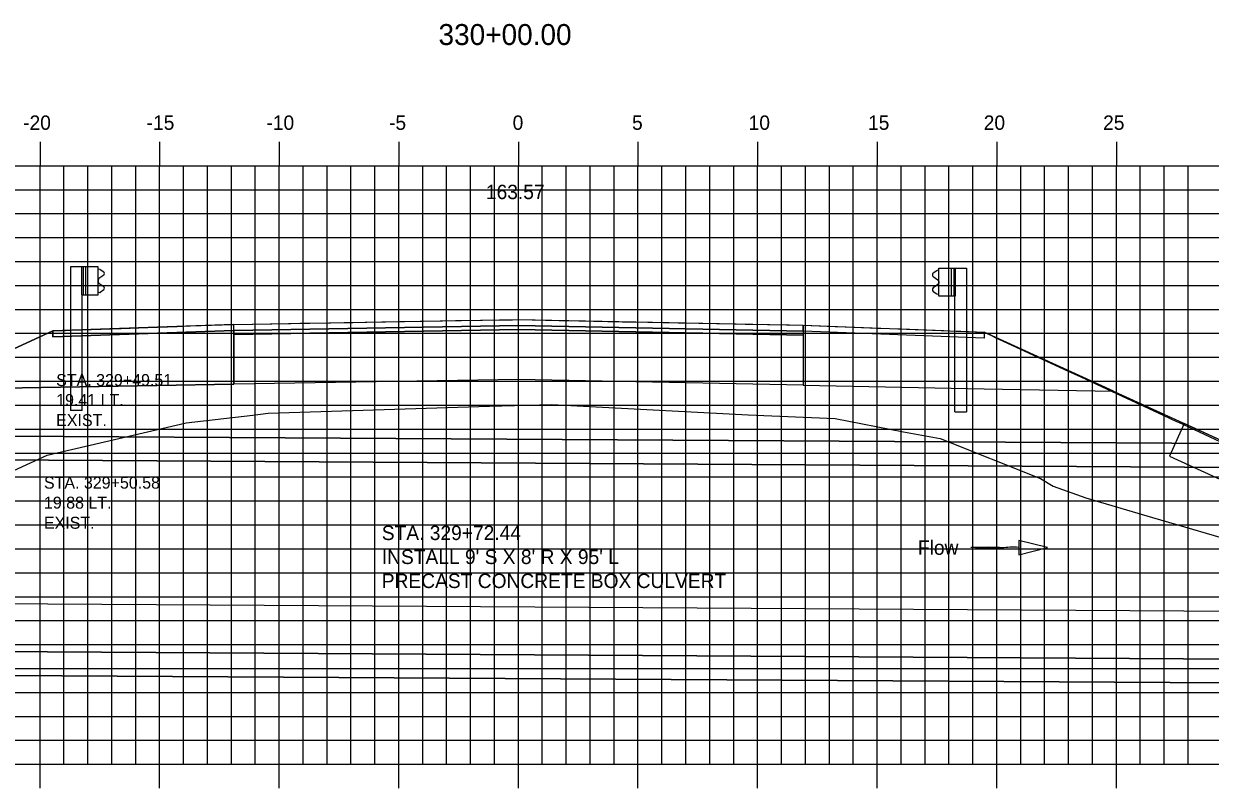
# Model space of a CAD drawing. Extents: x 1141202 to 1141372, y 608981 to 609091.
# Drawn here: x 1141264.83 to 1141314.44, y 609024.33 to 609056.27 of the extents above; entities that cross this region are included whole.
import ezdxf

# ---------------------------------------------------------------- set-up
doc = ezdxf.new("R2010")
doc.units = 0
for name, color, linetype in [('ANNOTATION', 7, 'Continuous'), ('D_Drainage_Culvert', 7, 'Continuous'), ('D_Guardrail_Beam_Lt', 7, 'Continuous'), ('D_Guardrail_Beam_Rt', 7, 'Continuous'), ('D_Guardrail_ConcBarrier', 7, 'Continuous'), ('D_Roadway_Centerline', 7, 'Continuous'), ('D_Roadway_Centerline_Text', 7, 'Continuous'), ('D_Roadway_Edge_Shoulder', 7, 'Continuous'), ('D_Roadway_Edge_TW', 7, 'Continuous'), ('D_Roadway_Pavement', 7, 'Continuous'), ('D_Roadway_SlopeLines', 7, 'Continuous'), ('D_Roadway_SubGrade', 7, 'Continuous'), ('D_Text_Monospaced', 7, 'Continuous'), ('H_V ANNOTATION', 7, 'Continuous'), ('MAJOR', 7, 'Continuous'), ('MINOR', 7, 'Continuous'), ('PATTERNING', 7, 'Continuous'), ('S_Roadway_Centerline', 7, 'Continuous'), ('WATER_DAM', 7, 'Continuous')]:
    doc.layers.add(name, color=color, linetype=linetype)

msp = doc.modelspace()

# ---------------------------------------------------------------- linework, layer by layer
for points in [[(1141264.248, 609042.614), (1141266.045, 609043.442), (1141266.046, 609043.442), (1141266.046, 609043.442), (1141266.454, 609043.456), (1141266.58, 609043.46), (1141266.817, 609043.469), (1141268.911, 609043.542), (1141270.019, 609043.581), (1141271.242, 609043.624), (1141271.801, 609043.644), (1141273.573, 609043.707), (1141273.583, 609043.707), (1141273.617, 609043.708), (1141275.902, 609043.747), (1141276.381, 609043.755), (1141276.526, 609043.757), (1141277.653, 609043.776), (1141278.232, 609043.786), (1141278.599, 609043.792), (1141279.11, 609043.801), (1141279.806, 609043.812), (1141280.561, 609043.825), (1141282.25, 609043.854), (1141282.889, 609043.864), (1141285.145, 609043.903), (1141285.217, 609043.904), (1141285.266, 609043.905), (1141285.514, 609043.909), (1141287.212, 609043.875), (1141287.544, 609043.868), (1141288.038, 609043.859), (1141289.871, 609043.822), (1141290.93, 609043.801), (1141292.198, 609043.776), (1141293.051, 609043.759), (1141294.524, 609043.73), (1141294.996, 609043.72), (1141296.849, 609043.684), (1141297.413, 609043.672), (1141298.76, 609043.621), (1141299.174, 609043.605), (1141300.539, 609043.553), (1141301.498, 609043.516), (1141303.307, 609043.447), (1141303.822, 609043.428), (1141304.016, 609043.42), (1141304.985, 609043.383)], [(1141305.345, 609043.216), (1141305.376, 609043.202), (1141305.396, 609043.193), (1141306.145, 609042.845), (1141307.41, 609042.26), (1141308.468, 609041.769), (1141309.026, 609041.511), (1141310.304, 609040.919), (1141310.791, 609040.694), (1141311.659, 609040.291), (1141312.468, 609039.917), (1141313.034, 609039.654), (1141313.113, 609039.618), (1141315.076, 609038.709), (1141315.434, 609038.543), (1141317.138, 609037.754), (1141317.755, 609037.468), (1141318.557, 609037.097), (1141320.075, 609036.394), (1141321.235, 609035.857), (1141322.395, 609035.32), (1141323.928, 609034.61), (1141324.715, 609034.246), (1141326.998, 609033.189)]]:
    msp.add_lwpolyline(points)
at = {"layer": 'D_Drainage_Culvert'}
for points in [[(1141240.936, 609030.185), (1141240.985, 609038.185), (1141240.991, 609039.185), (1141335.989, 609038.605), (1141335.983, 609037.605), (1141335.934, 609029.606), (1141335.916, 609026.606), (1141334.916, 609026.612), (1141334.928, 609028.612), (1141335.928, 609028.606), (1141240.93, 609029.185), (1141240.918, 609027.185), (1141241.918, 609027.179), (1141241.93, 609029.179)], [(1141240.934, 609030.185), (1141335.934, 609029.606), (1141335.983, 609037.605), (1141240.985, 609038.185), (1141240.936, 609030.185)]]:
    msp.add_lwpolyline(points, dxfattribs=at)
at = {"layer": 'D_Guardrail_Beam_Lt'}
for p, q in [((1141266.783, 609046.107), (1141266.783, 609040.107)), ((1141267.254, 609046.107), (1141266.783, 609046.107)), ((1141267.941, 609046.107), (1141267.254, 609046.107)), ((1141267.254, 609046.107), (1141267.254, 609044.941)), ((1141267.316, 609046.107), (1141267.316, 609044.941)), ((1141267.42, 609046.107), (1141267.42, 609044.941)), ((1141267.941, 609044.941), (1141267.941, 609046.107)), ((1141267.941, 609046.024), (1141268.015, 609046.009)), ((1141268.031, 609046.003), (1141268.175, 609045.903)), ((1141267.946, 609045.559), (1141267.946, 609045.489)), ((1141268.175, 609045.76), (1141267.979, 609045.624)), ((1141267.979, 609045.425), (1141268.175, 609045.288)), ((1141267.254, 609044.941), (1141267.941, 609044.941)), ((1141267.274, 609040.107), (1141267.274, 609044.941)), ((1141268.015, 609045.039), (1141267.941, 609045.024)), ((1141268.175, 609045.145), (1141268.031, 609045.045)), ((1141267.274, 609040.107), (1141266.783, 609040.107))]:
    msp.add_line(p, q, dxfattribs=at)
for centre, major_axis, start_param, end_param in [((1141268.007, 609045.969), (0.0417, 0), 0.959931, 1.376053), ((1141268.024, 609045.559), (-0.0789, 0), 5.323254, 6.283185), ((1141268.024, 609045.489), (-0.0789, 0), 6.283185, 7.243116), ((1141268.124, 609045.831), (0.0877, 0), 5.323254, 7.243116), ((1141268.007, 609045.079), (0.0417, 0), 4.907132, 5.323254), ((1141268.124, 609045.217), (0.0877, 0), 5.323254, 7.243116)]:
    msp.add_ellipse(centre, major_axis=major_axis, ratio=0.995501, start_param=start_param, end_param=end_param, dxfattribs=at)
at = {"layer": 'D_Guardrail_Beam_Rt'}
for p, q in [((1141303.003, 609045.946), (1141302.86, 609045.846)), ((1141303.093, 609045.967), (1141303.019, 609045.953)), ((1141302.86, 609045.703), (1141303.055, 609045.567)), ((1141303.089, 609045.503), (1141303.089, 609045.432)), ((1141303.055, 609045.368), (1141302.86, 609045.232)), ((1141302.86, 609045.089), (1141303.003, 609044.989)), ((1141303.019, 609044.982), (1141303.093, 609044.967))]:
    msp.add_line(p, q, dxfattribs=at)
for centre, major_axis, start_param, end_param in [((1141303.027, 609045.912), (-0.0417, 0), 4.907132, 5.323254), ((1141302.91, 609045.775), (-0.0877, 0), 5.323254, 7.243116), ((1141303.01, 609045.503), (0.0789, 0), 0, 0.959931), ((1141303.01, 609045.432), (0.0789, 0), 5.323254, 6.283185), ((1141302.91, 609045.16), (-0.0877, 0), 5.323254, 7.243116), ((1141303.027, 609045.023), (-0.0417, 0), 0.959931, 1.376053)]:
    msp.add_ellipse(centre, major_axis=major_axis, ratio=0.995501, start_param=start_param, end_param=end_param, dxfattribs=at)
at = {"layer": 'D_Guardrail_ConcBarrier'}
for p, q in [((1141303.093, 609046.051), (1141303.78, 609046.051)), ((1141303.093, 609044.884), (1141303.093, 609046.051)), ((1141303.614, 609046.051), (1141303.614, 609044.884)), ((1141303.718, 609046.051), (1141303.718, 609044.884)), ((1141303.78, 609046.051), (1141304.251, 609046.051)), ((1141303.78, 609046.051), (1141303.78, 609044.884)), ((1141304.251, 609046.051), (1141304.251, 609040.051)), ((1141303.78, 609044.884), (1141303.093, 609044.884)), ((1141303.76, 609040.051), (1141303.76, 609044.884)), ((1141303.76, 609040.051), (1141304.251, 609040.051))]:
    msp.add_line(p, q, dxfattribs=at)
at = {"layer": 'D_Roadway_Edge_Shoulder'}
for points in [[(1141273.617, 609043.708), (1141266.046, 609043.442), (1141266.046, 609043.192), (1141273.617, 609043.458)], [(1141297.413, 609043.672), (1141304.985, 609043.383), (1141304.985, 609043.133), (1141297.413, 609043.422)]]:
    msp.add_lwpolyline(points, close=True, dxfattribs=at)
at = {"layer": 'D_Roadway_Edge_TW'}
msp.add_lwpolyline([(1141273.617, 609043.458), (1141273.617, 609043.708), (1141285.514, 609043.909), (1141297.413, 609043.672), (1141297.413, 609043.422), (1141285.514, 609043.659)], close=True, dxfattribs=at)
at = {"layer": 'D_Roadway_Pavement'}
msp.add_lwpolyline([(1141273.617, 609043.291), (1141273.617, 609043.458), (1141285.514, 609043.659), (1141297.413, 609043.422), (1141297.413, 609043.256), (1141285.514, 609043.492)], close=True, dxfattribs=at)
at = {"layer": 'D_Roadway_SlopeLines'}
msp.add_lwpolyline([(1141273.617, 609041.209), (1141260.721, 609040.991), (1141266.047, 609043.443), (1141266.047, 609043.193), (1141273.617, 609043.459)], close=True, dxfattribs=at)
at = {"layer": 'D_Roadway_SubGrade'}
for points in [[(1141273.617, 609043.291), (1141273.617, 609043.458), (1141266.046, 609043.192), (1141266.046, 609043.442), (1141266.045, 609043.442), (1141260.728, 609040.994), (1141273.617, 609041.208)], [(1141273.617, 609041.208), (1141273.617, 609043.291), (1141285.514, 609043.492), (1141297.413, 609043.256), (1141297.413, 609041.172), (1141285.514, 609041.409)], [(1141304.985, 609041.023), (1141310.388, 609040.917), (1141304.985, 609043.383), (1141304.985, 609043.133), (1141297.413, 609043.422), (1141297.413, 609041.172)]]:
    msp.add_lwpolyline(points, close=True, dxfattribs=at)
msp.add_lwpolyline([(1141304.985, 609043.383), (1141320.188, 609036.444), (1141330.629, 609031.638)], dxfattribs=at)
at = {"layer": 'MAJOR'}
for p, q in [((1141265.514, 609051.337), (1141265.514, 609050.335)), ((1141270.514, 609051.337), (1141270.514, 609050.335)), ((1141275.514, 609051.337), (1141275.514, 609050.335)), ((1141280.514, 609051.337), (1141280.514, 609050.335)), ((1141285.514, 609051.337), (1141285.514, 609050.335)), ((1141290.514, 609051.337), (1141290.514, 609050.335)), ((1141295.514, 609051.337), (1141295.514, 609050.335)), ((1141300.514, 609051.337), (1141300.514, 609050.335)), ((1141305.514, 609051.337), (1141305.514, 609050.335)), ((1141310.514, 609051.337), (1141310.514, 609050.335)), ((1141215.514, 609050.335), (1141355.514, 609050.335)), ((1141215.514, 609050.335), (1141355.514, 609050.335)), ((1141265.514, 609025.335), (1141265.514, 609050.335)), ((1141270.514, 609025.335), (1141270.514, 609050.335)), ((1141275.514, 609025.335), (1141275.514, 609050.335)), ((1141280.514, 609025.335), (1141280.514, 609050.335)), ((1141285.514, 609025.335), (1141285.514, 609050.335)), ((1141290.514, 609025.335), (1141290.514, 609050.335)), ((1141295.514, 609025.335), (1141295.514, 609050.335)), ((1141300.514, 609025.335), (1141300.514, 609050.335)), ((1141305.514, 609025.335), (1141305.514, 609050.335)), ((1141310.514, 609025.335), (1141310.514, 609050.335)), ((1141215.514, 609045.335), (1141355.514, 609045.335)), ((1141215.514, 609040.335), (1141355.514, 609040.335)), ((1141215.514, 609035.335), (1141355.514, 609035.335)), ((1141215.514, 609030.335), (1141355.514, 609030.335)), ((1141215.514, 609025.335), (1141355.514, 609025.335)), ((1141215.514, 609025.335), (1141355.514, 609025.335)), ((1141265.514, 609024.333), (1141265.514, 609025.335)), ((1141270.514, 609024.333), (1141270.514, 609025.335)), ((1141275.514, 609024.333), (1141275.514, 609025.335)), ((1141280.514, 609024.333), (1141280.514, 609025.335)), ((1141285.514, 609024.333), (1141285.514, 609025.335)), ((1141290.514, 609024.333), (1141290.514, 609025.335)), ((1141295.514, 609024.333), (1141295.514, 609025.335)), ((1141300.514, 609024.333), (1141300.514, 609025.335)), ((1141305.514, 609024.333), (1141305.514, 609025.335)), ((1141310.514, 609024.333), (1141310.514, 609025.335))]:
    msp.add_line(p, q, dxfattribs=at)
at = {"layer": 'MINOR'}
for p, q in [((1141266.514, 609025.335), (1141266.514, 609050.335)), ((1141267.514, 609025.335), (1141267.514, 609050.335)), ((1141268.514, 609025.335), (1141268.514, 609050.335)), ((1141269.514, 609025.335), (1141269.514, 609050.335)), ((1141271.514, 609025.335), (1141271.514, 609050.335)), ((1141272.514, 609025.335), (1141272.514, 609050.335)), ((1141273.514, 609025.335), (1141273.514, 609050.335)), ((1141274.514, 609025.335), (1141274.514, 609050.335)), ((1141276.514, 609025.335), (1141276.514, 609050.335)), ((1141277.514, 609025.335), (1141277.514, 609050.335)), ((1141278.514, 609025.335), (1141278.514, 609050.335)), ((1141279.514, 609025.335), (1141279.514, 609050.335)), ((1141281.514, 609025.335), (1141281.514, 609050.335)), ((1141282.514, 609025.335), (1141282.514, 609050.335)), ((1141283.514, 609025.335), (1141283.514, 609050.335)), ((1141284.514, 609025.335), (1141284.514, 609050.335)), ((1141286.514, 609025.335), (1141286.514, 609050.335)), ((1141287.514, 609025.335), (1141287.514, 609050.335)), ((1141288.514, 609025.335), (1141288.514, 609050.335)), ((1141289.514, 609025.335), (1141289.514, 609050.335)), ((1141291.514, 609025.335), (1141291.514, 609050.335)), ((1141292.514, 609025.335), (1141292.514, 609050.335)), ((1141293.514, 609025.335), (1141293.514, 609050.335)), ((1141294.514, 609025.335), (1141294.514, 609050.335)), ((1141296.514, 609025.335), (1141296.514, 609050.335)), ((1141297.514, 609025.335), (1141297.514, 609050.335)), ((1141298.514, 609025.335), (1141298.514, 609050.335)), ((1141299.514, 609025.335), (1141299.514, 609050.335)), ((1141301.514, 609025.335), (1141301.514, 609050.335)), ((1141302.514, 609025.335), (1141302.514, 609050.335)), ((1141303.514, 609025.335), (1141303.514, 609050.335)), ((1141304.514, 609025.335), (1141304.514, 609050.335)), ((1141306.514, 609025.335), (1141306.514, 609050.335)), ((1141307.514, 609025.335), (1141307.514, 609050.335)), ((1141308.514, 609025.335), (1141308.514, 609050.335)), ((1141309.514, 609025.335), (1141309.514, 609050.335)), ((1141311.514, 609025.335), (1141311.514, 609050.335)), ((1141312.514, 609025.335), (1141312.514, 609050.335)), ((1141313.514, 609025.335), (1141313.514, 609050.335)), ((1141215.514, 609049.335), (1141355.514, 609049.335)), ((1141215.514, 609048.335), (1141355.514, 609048.335)), ((1141215.514, 609047.335), (1141355.514, 609047.335)), ((1141215.514, 609046.335), (1141355.514, 609046.335)), ((1141215.514, 609044.335), (1141355.514, 609044.335)), ((1141215.514, 609043.335), (1141355.514, 609043.335)), ((1141215.514, 609042.335), (1141355.514, 609042.335)), ((1141215.514, 609041.335), (1141355.514, 609041.335)), ((1141215.514, 609039.335), (1141355.514, 609039.335)), ((1141215.514, 609038.335), (1141355.514, 609038.335)), ((1141215.514, 609037.335), (1141355.514, 609037.335)), ((1141215.514, 609036.335), (1141355.514, 609036.335)), ((1141215.514, 609034.335), (1141355.514, 609034.335)), ((1141215.514, 609033.335), (1141355.514, 609033.335)), ((1141215.514, 609032.335), (1141355.514, 609032.335)), ((1141215.514, 609031.335), (1141355.514, 609031.335)), ((1141215.514, 609029.335), (1141355.514, 609029.335)), ((1141215.514, 609028.335), (1141355.514, 609028.335)), ((1141215.514, 609027.335), (1141355.514, 609027.335)), ((1141215.514, 609026.335), (1141355.514, 609026.335))]:
    msp.add_line(p, q, dxfattribs=at)
at = {"layer": 'PATTERNING'}
for points in [[(1141330.629, 609031.638), (1141322.005, 609035.607), (1141313.354, 609039.563), (1141312.731, 609038.198), (1141327.056, 609031.66)], [(1141240.991, 609039.185), (1141240.985, 609038.185), (1141335.983, 609037.605), (1141335.989, 609038.605)], [(1141335.946, 609031.606), (1141335.934, 609029.606), (1141240.934, 609030.185), (1141240.946, 609032.185)], [(1141335.928, 609028.606), (1141335.934, 609029.606), (1141240.934, 609030.185), (1141240.93, 609029.185)]]:
    msp.add_lwpolyline(points, close=True, dxfattribs=at)
at = {"layer": 'S_Roadway_Centerline'}
msp.add_lwpolyline([(1141238.303, 609032.434), (1141240.853, 609032.205), (1141243.375, 609032.577), (1141245.2, 609032.879), (1141251.055, 609034.71), (1141251.563, 609035.05), (1141259.713, 609035.449), (1141265.819, 609038.239), (1141271.628, 609039.59), (1141274.411, 609039.914), (1141275.053, 609040.002), (1141284.311, 609040.287), (1141286.912, 609040.365), (1141295.122, 609039.926), (1141298.757, 609039.782), (1141301.617, 609039.219), (1141303.144, 609038.939), (1141307.342, 609037.277), (1141307.866, 609036.952), (1141309.238, 609036.47), (1141312.023, 609035.648), (1141315.938, 609034.498)], dxfattribs=at)
at = {"layer": 'WATER_DAM'}
msp.add_lwpolyline([(1141307.635, 609034.384), (1141306.435, 609034.684), (1141306.435, 609034.084)], close=True, dxfattribs=at)
msp.add_open_spline([(1141306.435, 609034.384), (1141306.185, 609034.434), (1141305.685, 609034.334), (1141305.185, 609034.434), (1141304.685, 609034.334), (1141304.435, 609034.384), (1141306.435, 609034.384), (1141304.435, 609034.384)], degree=3, dxfattribs=at)

# ---------------------------------------------------------------- texts
at = {"layer": 'ANNOTATION'}
for s, p in [('STA. 329+72.44', (1141279.802, 609034.7)), ("INSTALL 9' S X 8' R X 95' L", (1141279.802, 609033.698)), ('PRECAST CONCRETE BOX CULVERT', (1141279.802, 609032.696))]:
    msp.add_text(s, height=0.6, dxfattribs=at).set_placement(p)
at = {"layer": 'D_Roadway_Centerline'}
for s, p in [('C', (1141285.509, 609043.91)), ('C', (1141285.509, 609043.909)), ('L', (1141285.515, 609043.903)), ('L', (1141285.514, 609043.902))]:
    msp.add_text(s, height=0.0146, dxfattribs=at).set_placement(p)
at = {"layer": 'D_Roadway_Centerline_Text'}
msp.add_text('163.57', height=0.6, dxfattribs=at).set_placement((1141284.155, 609048.941))
at = {"layer": 'D_Text_Monospaced'}
for s, height, p in [('STA. 329+49.51', 0.49998, (1141266.189, 609041.134)), ('19.41 LT.', 0.5, (1141266.189, 609040.3)), ('EXIST. ', 0.5, (1141266.189, 609039.46)), ('STA. 329+50.58', 0.49998, (1141265.678, 609036.847)), ('19.88 LT.', 0.5, (1141265.678, 609036.013)), ('EXIST. ', 0.5, (1141265.678, 609035.173))]:
    msp.add_text(s, height=height, dxfattribs=at).set_placement(p)
at = {"layer": 'H_V ANNOTATION'}
for s, height, p in [('330+00.00', 0.875, (1141282.174, 609055.378)), ('-20', 0.6, (1141264.808, 609051.835)), ('-15', 0.6, (1141269.971, 609051.835)), ('-10', 0.6, (1141274.979, 609051.835)), ('-5', 0.6, (1141280.105, 609051.835)), ('0', 0.6, (1141285.273, 609051.835)), ('5', 0.6, (1141290.265, 609051.835)), ('10', 0.6, (1141295.14, 609051.835)), ('15', 0.6, (1141300.131, 609051.835)), ('20', 0.6, (1141304.968, 609051.835)), ('25', 0.6, (1141309.96, 609051.835))]:
    msp.add_text(s, height=height, dxfattribs=at).set_placement(p)
at = {"layer": 'S_Roadway_Centerline'}
for s, p in [('C', (1141286.907, 609040.365)), ('L', (1141286.912, 609040.358))]:
    msp.add_text(s, height=0.0146, dxfattribs=at).set_placement(p)
at = {"layer": 'WATER_DAM'}
msp.add_text('Flow', height=0.6, dxfattribs=at).set_placement((1141302.217, 609034.084))

doc.saveas('drawing.dxf')
